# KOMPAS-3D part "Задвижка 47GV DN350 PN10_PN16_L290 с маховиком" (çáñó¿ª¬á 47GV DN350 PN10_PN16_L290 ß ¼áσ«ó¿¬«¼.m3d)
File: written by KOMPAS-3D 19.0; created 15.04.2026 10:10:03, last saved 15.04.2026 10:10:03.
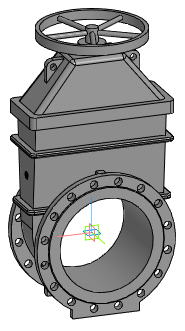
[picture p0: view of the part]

Document properties: Автор: Евгений; Полное имя файла: Z:\3.Личные\kachalov\3d для проектировщиков\2.1 Тип 47GV, 47GV.Z\Задвижка 47GV_DN40-DN600\stp_Задвижка 47GV\Задвижка 47GV DN350 PN10_PN16_L290 с маховиком.m3d

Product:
- Part/product: Задвижка 47GV DN350 PN10_PN16_L290 с маховиком

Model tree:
1. Операция без истории:1  (labels: Задвижка 47GV DN350 PN10_PN16_L290 с маховиком)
